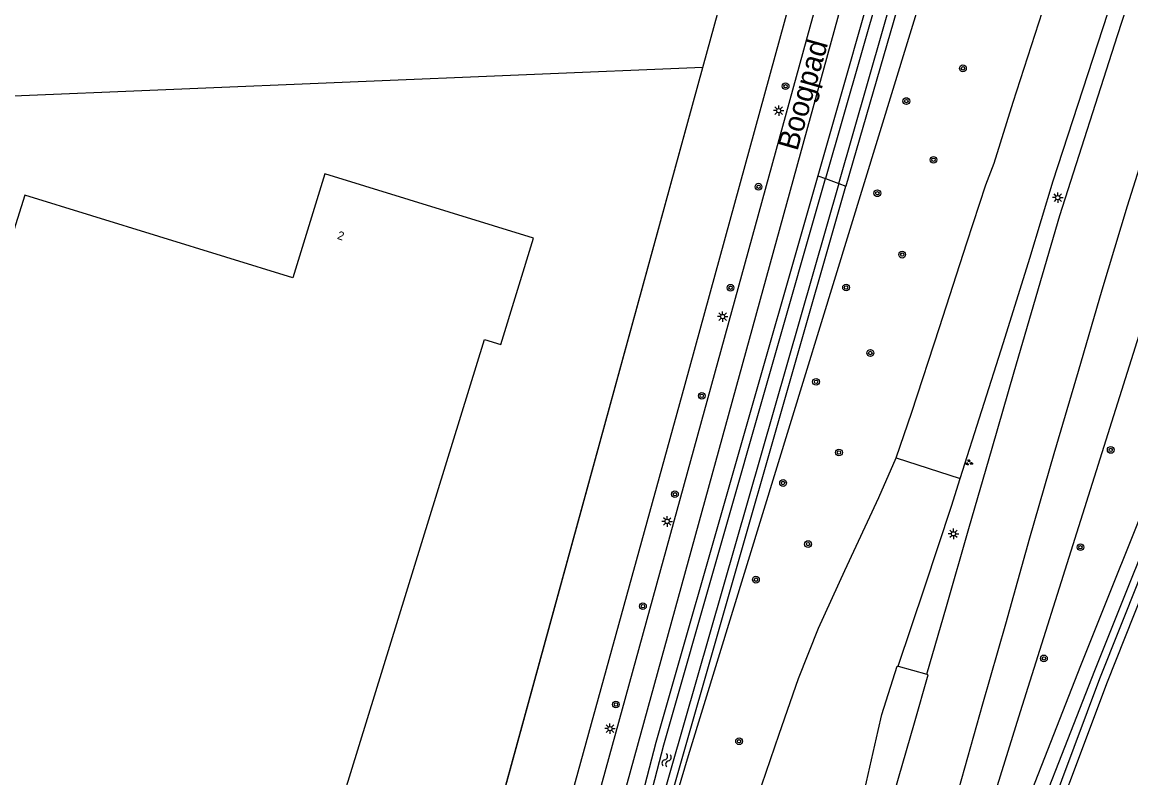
# Model space of a CAD drawing. Extents: x 131000 to 133013, y 393000 to 396501.
# Drawn here: x 131131.4 to 131262.9, y 393663.2 to 393752.8 of the extents above; entities that cross this region are included whole.
import ezdxf

# ---------------------------------------------------------------- set-up
doc = ezdxf.new("R2010")
doc.units = 0
for name, color, linetype in [('gg-afsc-hekwerk', 7, 'Continuous'), ('gg-anno-huisnummerreeks BGT', 7, 'Continuous'), ('gg-anno-openbare ruimte label', 7, 'Continuous'), ('gg-bbg-hoofdgebouw', 7, 'Continuous'), ('gg-knt-BGT kruinlijn', 7, 'Continuous'), ('gg-knt-verharding', 7, 'Continuous'), ('gg-kntw-bovenkant insteek waterloop', 7, 'Continuous'), ('gg-kntw-waterlijn', 7, 'Continuous'), ('gt-grn-groengrens', 7, 'Continuous'), ('gt-grn-vlakafsluiter', 7, 'Continuous'), ('gt-symb-boom', 7, 'Continuous'), ('gt-symb-groenvak', 7, 'Continuous'), ('gt-symb-lichtmast', 7, 'Continuous'), ('gt-symb-watersymbool', 7, 'Continuous'), ('gx-grn-maaiveld', 7, 'Continuous')]:
    doc.layers.add(name, color=color, linetype=linetype)

# ---------------------------------------------------------------- blocks, each defined once
blk = doc.blocks.new('gt0-LMAST')
at = {"layer": 'gt-symb-lichtmast'}
for p, q in [((-0.18, 0.17), (-0.45, 0.44)), ((-0.01, 0.25), (-0.01, 0.62)), ((0.17, 0.17), (0.44, 0.44)), ((-0.26, 0), (-0.63, 0)), ((-0.18, -0.18), (-0.45, -0.45)), ((-0.01, -0.25), (-0.01, -0.63)), ((0.44, -0.45), (0.17, -0.18)), ((0.24, 0), (0.62, 0))]:
    blk.add_line(p, q, dxfattribs=at)
blk.add_circle((-0.01, 0), 0.25, dxfattribs=at)
blk = doc.blocks.new('gt0-BOOM')
at = {"layer": 'gt-symb-boom'}
for radius in [0.4, 0.2]:
    blk.add_circle((0, 0), radius, dxfattribs=at)
blk = doc.blocks.new('gt0-WA')
at = {"layer": 'gt-symb-watersymbool'}
for centre, start, end in [((-0.32, 0.02), 28.0725, 151.9275), ((0.43, 0.42), 208.0725, 331.9275), ((-0.32, -0.43), 28.0725, 151.9275), ((0.43, -0.03), 208.0725, 331.9275)]:
    blk.add_arc(centre, 0.425, start, end, dxfattribs=at)
blk = doc.blocks.new('gt0-GRVAK')
at = {"layer": 'gt-symb-groenvak'}
for p, q in [((-0.11, 0.19), (-0.23, 0.24)), ((-0.18, 0.15), (0.09, 0.15)), ((-0.09, 0.21), (-0.16, 0.32)), ((-0.05, 0.21), (-0.05, 0.39)), ((0, 0.21), (0.06, 0.32)), ((0.02, 0.19), (0.13, 0.24)), ((0.26, -0.05), (0.2, 0.06)), ((0.31, -0.05), (0.31, 0.13)), ((0.35, -0.05), (0.41, 0.06)), ((-0.24, -0.23), (-0.36, -0.18)), ((-0.32, -0.26), (-0.05, -0.26)), ((-0.23, -0.21), (-0.29, -0.09)), ((-0.18, -0.2), (-0.18, -0.02)), ((-0.14, -0.21), (-0.07, -0.09)), ((-0.12, -0.23), (0, -0.18)), ((0.24, -0.07), (0.12, -0.02)), ((0.17, -0.11), (0.44, -0.11)), ((0.37, -0.07), (0.49, -0.02))]:
    blk.add_line(p, q, dxfattribs=at)

msp = doc.modelspace()

# ---------------------------------------------------------------- linework, layer by layer
at = {"layer": 'gg-afsc-hekwerk'}
for p, q in [((131212.15, 393747.43), (131045.94, 393740.53)), ((131212.15, 393747.43), (131045.94, 393740.53)), ((131184.5, 393646.61), (131212.15, 393747.43))]:
    msp.add_line(p, q, dxfattribs=at)
for points in [[(131212.15, 393747.43), (131248.52, 393879.83), (131064.61, 393832.73), (131000, 393827.51)], [(131174.79, 393649.57), (131184.5, 393646.61), (131212.15, 393747.43)]]:
    msp.add_lwpolyline(points, dxfattribs=at)
at = {"layer": 'gg-bbg-hoofdgebouw'}
msp.add_lwpolyline([(131166.79, 393652.01), (131186.26, 393715.17), (131188.19, 393714.58), (131192.08, 393727.2), (131167.33, 393734.84), (131163.52, 393722.49), (131131.74, 393732.3), (131112, 393669.54), (131111.55, 393669.68), (131111.4, 393669.17), (131104.91, 393671.17), (131101.85, 393661.26)], dxfattribs=at)
at = {"layer": 'gg-knt-BGT kruinlijn'}
msp.add_lwpolyline([(131193.66, 393609.27), (131210.48, 393665.82), (131239.99, 393762.02), (131262.31, 393836.26), (131276.8, 393892.47)], dxfattribs=at)
at = {"layer": 'gg-knt-verharding'}
for p, q in [((131235.08, 393701.13), (131242.69, 393698.7)), ((131235.32, 393676.41), (131238.75, 393675.47))]:
    msp.add_line(p, q, dxfattribs=at)
for points in [[(131179.34, 393602.3), (131179.27, 393602.94), (131179.36, 393603.56), (131179.55, 393604.1), (131179.73, 393604.4), (131180.17, 393604.93), (131180.8, 393605.51), (131182.9, 393607.27), (131184.9, 393609.12), (131186.28, 393610.51), (131186.88, 393611.17), (131188.33, 393612.98), (131189.11, 393614.13), (131191.39, 393618.91), (131193.17, 393626.12), (131286.07, 393963.69)], [(131235.08, 393701.13), (131236.96, 393706.57), (131240.24, 393716.6), (131243.47, 393726.64), (131245.74, 393733.51), (131246.71, 393736.11), (131248.99, 393743.31), (131252.9, 393755.48), (131256.73, 393767.3), (131256.97, 393768.04), (131264.21, 393790.47), (131270.7, 393810.69), (131277.73, 393832.74), (131284.21, 393853.43), (131290.64, 393874.66), (131297.66, 393898.34)], [(131238.75, 393675.47), (131241.06, 393683.48), (131243.71, 393692.77), (131246.47, 393702.29), (131249.07, 393711.34), (131254.5, 393729.9), (131261.36, 393751.22), (131277.58, 393801.19), (131292.25, 393847.41), (131298.25, 393867.1), (131304.13, 393886.82)], [(131242.69, 393698.7), (131247.82, 393714.8), (131250.96, 393724.82), (131253.73, 393733.99), (131260.19, 393753.87), (131271.07, 393787.56), (131277.76, 393808.55), (131284.63, 393830.27), (131291.17, 393851.17), (131297.63, 393872.27), (131301.97, 393887.27)], [(131258.15, 393873.58), (131237.39, 393797.83), (131194.93, 393643.44)], [(131220.25, 393591.52), (131221.81, 393596.29), (131224.98, 393605.73), (131228.08, 393615.05), (131230.96, 393623.82), (131233.97, 393633.16), (131236.9, 393642.53), (131239.8, 393652.21), (131242.54, 393661.84), (131245.38, 393671.95), (131248.1, 393681.44), (131250.95, 393691.66), (131253.85, 393701.65), (131256.7, 393711.41), (131259.54, 393721.05), (131262.53, 393731.02), (131265.43, 393740.18), (131268.43, 393749.36), (131284.4, 393798.64)], [(131198.05, 393599), (131201.51, 393609.4), (131202.58, 393612.61), (131204.86, 393619.39), (131205.59, 393621.55), (131208.7, 393630.88), (131211.79, 393640.1), (131215.02, 393649.74), (131218.14, 393659.35), (131221.2, 393668.36), (131223.51, 393674.97), (131225.9, 393680.91), (131229.01, 393687.78), (131233.05, 393696.42), (131235.08, 393701.13)], [(131235.32, 393676.41), (131238.51, 393685.84), (131241.65, 393695.42), (131242.69, 393698.7)], [(131212.47, 393598.88), (131212.6, 393599.27), (131214.84, 393605.99), (131217.18, 393613.05), (131219.89, 393621.18), (131220.94, 393624.39), (131224.13, 393633.91), (131226.97, 393642.42), (131227.44, 393644.33), (131229.4, 393653.1), (131231.17, 393660.97), (131232.94, 393668.78), (131233.41, 393670.68), (131235.22, 393676.42), (131235.32, 393676.41)], [(131214.85, 393597.86), (131216.51, 393602.86), (131219.56, 393612.05), (131222.14, 393619.96), (131222.85, 393622.14), (131225.83, 393631.39), (131228.81, 393640.9), (131231.66, 393650.34), (131234.44, 393659.85), (131237.25, 393669.71), (131238.88, 393675.4), (131238.75, 393675.47)]]:
    msp.add_lwpolyline(points, dxfattribs=at)
at = {"layer": 'gg-kntw-bovenkant insteek waterloop'}
msp.add_line((131193.66, 393609.27), (131229.11, 393733.38), dxfattribs=at)
for points in [[(131269.82, 393892.57), (131261.58, 393861.59), (131255.13, 393838.09), (131234.23, 393764.14), (131225.79, 393734.6)], [(131225.79, 393734.6), (131206.58, 393667.35), (131191.81, 393610.41), (131193.66, 393609.27)], [(131230.52, 393600.85), (131231.45, 393602.69), (131232.59, 393604.66), (131240.28, 393624.09), (131251.11, 393650.44), (131260.14, 393674.57), (131269.61, 393698.35), (131271.63, 393703.36)]]:
    msp.add_lwpolyline(points, dxfattribs=at)
at = {"layer": 'gg-kntw-waterlijn'}
for points in [[(131271.77, 393892.79), (131271.59, 393892.1), (131262.55, 393861.33), (131256.09, 393837.82), (131235.19, 393763.87), (131226.73, 393734.26)], [(131228.28, 393733.69), (131261.39, 393849.18), (131273.43, 393892.97)], [(131228.28, 393733.69), (131193.06, 393610.81), (131192.96, 393610.88), (131207.55, 393667.09), (131226.73, 393734.26)], [(131268.68, 393698.72), (131259.21, 393674.93), (131250.18, 393650.81), (131239.35, 393624.47), (131231.66, 393606.12), (131229.94, 393601.8), (131229.84, 393600.92), (131229.09, 393601), (131229.34, 393602.9), (131231.14, 393606.93), (131233.16, 393611.33), (131239.05, 393626.6), (131248.96, 393651.15), (131258.65, 393675.9), (131268.26, 393699.9)]]:
    msp.add_lwpolyline(points, dxfattribs=at)
at = {"layer": 'gt-grn-groengrens'}
for points in [[(131231.47, 393611.89), (131249.85, 393671.04), (131317.03, 393884.15)], [(131184.12, 393613.3), (131184.3, 393614.9), (131185.56, 393620.18), (131190.77, 393639.96), (131210.07, 393709.88), (131228.41, 393776.78), (131242.98, 393829.13), (131244.9, 393836.58), (131254.75, 393872.74)]]:
    msp.add_lwpolyline(points, dxfattribs=at)
at = {"layer": 'gt-grn-vlakafsluiter'}
for p, q in [((131225.79, 393734.6), (131226.73, 393734.26)), ((131226.73, 393734.26), (131228.28, 393733.69)), ((131228.28, 393733.69), (131229.11, 393733.38))]:
    msp.add_line(p, q, dxfattribs=at)
at = {"layer": 'gx-grn-maaiveld'}
msp.add_line((131275.32, 393892.75), (131229.11, 393733.38), dxfattribs=at)
msp.add_lwpolyline([(131332.62, 393880.89), (131327.04, 393858.19), (131322.4, 393844.52), (131313.48, 393820.13), (131303.96, 393796.17), (131294.53, 393772.13), (131285.09, 393748.48), (131266.58, 393700.47), (131256.97, 393676.47), (131247.27, 393651.72), (131237.37, 393627.16), (131231.47, 393611.89)], dxfattribs=at)

# ---------------------------------------------------------------- block references
at = {"layer": 'gt-symb-boom'}
for p in [(131243.01, 393747.34), (131221.98, 393745.22), (131236.3, 393743.46), (131239.52, 393736.49), (131218.77, 393733.3), (131232.86, 393732.52), (131235.81, 393725.24), (131215.45, 393721.31), (131229.15, 393721.34), (131232.03, 393713.57), (131225.59, 393710.15), (131212.04, 393708.49), (131228.31, 393701.77), (131260.54, 393702.07), (131221.68, 393698.15), (131208.85, 393696.82), (131224.64, 393690.9), (131256.95, 393690.53), (131218.46, 393686.68), (131205.06, 393683.54), (131252.62, 393677.34), (131201.85, 393671.87), (131216.46, 393667.51)]:
    msp.add_blockref('gt0-BOOM', p, dxfattribs=at)
at = {"layer": 'gt-symb-groenvak', "rotation": -11.13011108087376}
msp.add_blockref('gt0-GRVAK', (131243.73, 393700.56), dxfattribs=at)
at = {"layer": 'gt-symb-lichtmast'}
for p in [(131221.17, 393742.32), (131254.27, 393732), (131214.52, 393717.89), (131207.94, 393693.59), (131241.9, 393692.12), (131201.16, 393669.01)]:
    msp.add_blockref('gt0-LMAST', p, dxfattribs=at)
at = {"layer": 'gt-symb-watersymbool', "rotation": 74.04673812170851}
msp.add_blockref('gt0-WA', (131207.85, 393665.21), dxfattribs=at)

# ---------------------------------------------------------------- texts
at = {"layer": 'gg-anno-huisnummerreeks BGT'}
msp.add_text('2', height=1, rotation=342.8, dxfattribs=at).set_placement((131168.73, 393727.12))
at = {"layer": 'gg-anno-openbare ruimte label'}
msp.add_text('Boogpad', height=2.5, rotation=74.1, dxfattribs=at).set_placement((131223.37, 393737.45))

doc.saveas('drawing.dxf')
